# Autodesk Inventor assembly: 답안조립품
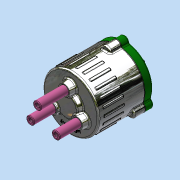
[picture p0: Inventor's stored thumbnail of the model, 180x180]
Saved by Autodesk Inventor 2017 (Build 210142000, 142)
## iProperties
Part Number: 답안조립품
Material: 일반
Document SubType Name: Assembly
Designer: MRC
Author: MRC
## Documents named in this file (15)
- C:\Users\MRC\Desktop\620811V1003\답안조립품.iam
- C:\Users\MRC\Desktop\620811V1003\본체.ipt
- C:\Users\MRC\Desktop\620811V1003\가변스프링1.ipt
- C:\Users\MRC\Desktop\620811V1003\가변스프링2.ipt
- C:\Users\MRC\Desktop\620811V1003\가변스프링3.ipt
- C:\Users\MRC\Desktop\620811V1003\개스킷.ipt
- C:\Users\MRC\Desktop\620811V1003\멈춤링 10x1.ipt
- C:\Users\MRC\Desktop\620811V1003\멈춤링 22x1.2.ipt
- C:\Users\MRC\Desktop\620811V1003\메인 축.ipt
- C:\Users\MRC\Desktop\620811V1003\베어링 NA 4900.ipt
- C:\Users\MRC\Desktop\620811V1003\볼트 M5.ipt
- C:\Users\MRC\Desktop\620811V1003\슬라이드 축.ipt
- C:\Users\MRC\Desktop\620811V1003\오일 실.ipt
- C:\Users\MRC\Desktop\620811V1003\커버.ipt
- C:\Users\MRC\Desktop\620811V1003\판캠.ipt
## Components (4 placed, 4 different names)
1. 가변스프링1:1
2. 가변스프링2:1
3. 가변스프링3:1
4. 개스킷:1
